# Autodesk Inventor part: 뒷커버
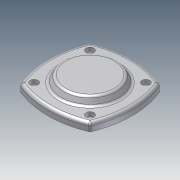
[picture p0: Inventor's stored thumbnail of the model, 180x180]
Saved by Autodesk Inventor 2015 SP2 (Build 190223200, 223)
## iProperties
Created: 2013-02
Part Number: 뒷커버
Document SubType Name: Modeling
Designer: 한국산업디자인학원[gmhk.co.kr]
Density: 1 g/cm^3
Material: 일반
Appearance: 기본값
Mass: 83.2003 g
Surface Area: 194.999 cm^2
Volume: 83.2003 cm^3
Author: 한국산업디자인학원[gmhk.co.kr]
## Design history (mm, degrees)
sketch "스케치1"
  geometry: C1 r 30 at (0, 0) reference; A1 r 91.05 centre (0, -48.55) between (34.185, 35.839) and (-34.185, 35.839) reference; A2 r 91.05 centre (48.55, 0) between (-35.839, 34.185) and (-35.839, -34.185) reference; A3 r 3 centre (-33.058, 33.058) between (-34.185, 35.839) and (-35.839, 34.185) reference; A4 r 3 centre (33.058, 33.058) between (35.839, 34.185) and (34.185, 35.839) reference; A5 r 91.05 centre (-48.55, 0) between (35.839, -34.185) and (35.839, 34.185) reference; A6 r 3 centre (33.058, -33.058) between (34.185, -35.839) and (35.839, -34.185) reference; A7 r 91.05 centre (0, 48.55) between (-34.185, -35.839) and (34.185, -35.839) reference; A8 r 3 centre (-33.058, -33.058) between (-35.839, -34.185) and (-34.185, -35.839) reference; 1 further point
  node "참조1"
  node "참조2"
  node "참조3"
  node "참조4"
  node "참조5"
  node "참조6"
  node "참조7"
  node "참조8"
  node "참조9"
extrude "돌출1" new body sketch "스케치1" distance "d0" = 8; taper "d1" = 0 deg
sketch "스케치2"
  geometry: C1 r 30 at (0, 0); 1 further point
  constraints: 1 centre point, 1 coincident
  dimensions: "d2" = 60 diameter of C1
extrude "돌출2" join sketch "스케치2" distance "d3" = 7; taper "d4" = -30 deg
sketch "스케치3"
  geometry: C1 r 1.621 at (28.284, 28.284) reference; C2 r 1.621 at (-28.284, 28.284) reference; C3 r 1.621 at (-28.284, -28.284) reference; C4 r 1.621 at (28.284, -28.284) reference; 1 further point
hole "구멍2" sketch "스케치3" at (28.284, 28.284), (28.284, -28.284), (-28.284, -28.284), (-28.284, 28.284) diameter "d14" = 4.5; stored, may be unused: countersink angle "d18" = 90 deg, drill point angle "d20" = 118 deg; dims "d15" = 6, "d16" = 8, "d17" = 4.4, "d19" = 20
extrude "돌출3" join sketch "스케치1" distance "d21" = 12; taper "d22" = 0 deg
hole "구멍3" diameter "d25" = 30; stored, may be unused: countersink angle "d29" = 90 deg, drill point angle "d31" = 0 deg; dims "d23" = 10, "d24" = 10, "d26" = 6, "d27" = 40, "d28" = 12, "d30" = 15
fillet "모깎기1" dims "d32" = 3, "d33" = 0.3
chamfer "모따기1" distance "d34" = 1; stored, may be unused: second distance "d35" = 2, angle "d36" = 45 deg
node "솔리드1"
node "참조10"
node "참조11"
node "참조12"
node "참조13"
